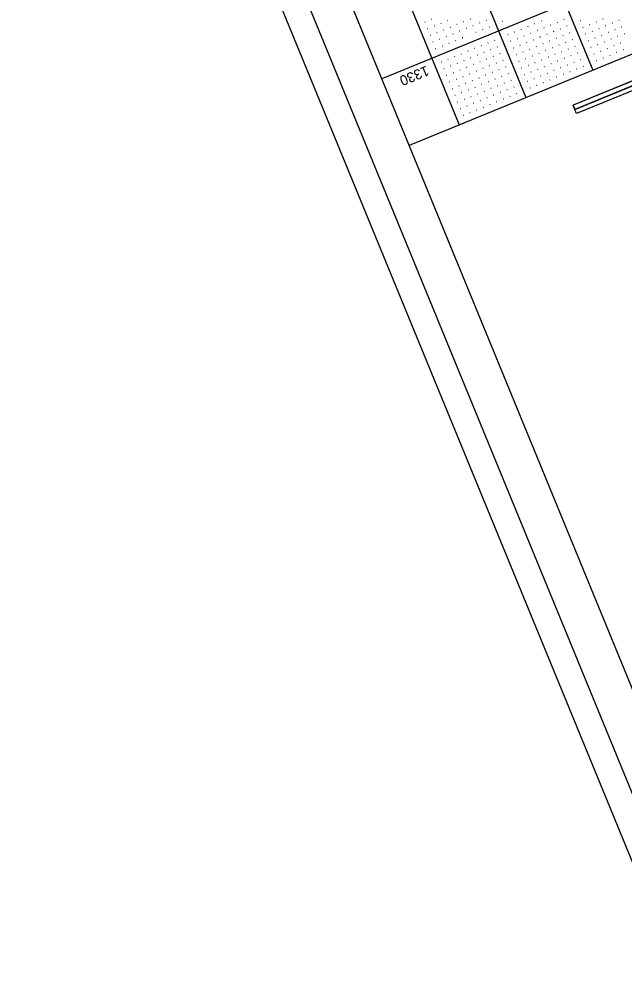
# Model space of a CAD drawing. Extents: x 2148770 to 2150891, y 142633 to 144465.
# Drawn here: x 2148770 to 2149190, y 142633 to 143292 of the extents above; entities that cross this region are included whole.
import ezdxf

# ---------------------------------------------------------------- set-up
doc = ezdxf.new("R2010")
doc.units = 0
for name, color, linetype in [('SHT_Plan_Profile_Sheet_Elev_Txt', 7, 'Continuous'), ('SHT_Plot_Shape_Full', 7, 'Continuous'), ('SHT_Plot_Shape_Half', 7, 'Continuous'), ('SHT_Profile_Grid_Major', 7, 'Continuous'), ('SHT_Profile_Grid_Minor', 7, 'Continuous'), ('SHT_Scale', 7, 'Continuous'), ('SHT_Sheet_Border', 7, 'Continuous')]:
    doc.layers.add(name, color=color, linetype=linetype)

msp = doc.modelspace()

# ---------------------------------------------------------------- linework, layer by layer
at = {"layer": 'SHT_Plot_Shape_Full'}
msp.add_lwpolyline([(2150890.55, 143316.95), (2149225.42, 142633.31), (2148769.66, 143743.39), (2150434.78, 144427.04)], close=True, dxfattribs=at)
at = {"layer": 'SHT_Plot_Shape_Half'}
msp.add_lwpolyline([(2150799.14, 143324.02), (2149226.52, 142678.36), (2148808.74, 143695.93), (2150381.36, 144341.59)], close=True, dxfattribs=at)
at = {"layer": 'SHT_Profile_Grid_Major'}
for p, q in [((2150478.22, 143848.96), (2149021.23, 143250.78)), ((2149015.5, 143626.78), (2149167.42, 143256.75)), ((2148969.25, 143607.79), (2149121.17, 143237.76))]:
    msp.add_line(p, q, dxfattribs=at)
at = {"layer": 'SHT_Profile_Grid_Minor'}
for p, q in [((2149051.17, 143290.09), (2149050.94, 143290)), ((2149055.79, 143291.99), (2149055.56, 143291.9)), ((2149066.94, 143291.17), (2149066.71, 143291.07)), ((2149078.09, 143290.34), (2149077.86, 143290.24)), ((2149082.72, 143292.24), (2149082.49, 143292.14)), ((2149089.24, 143289.51), (2149089.01, 143289.42)), ((2149093.87, 143291.41), (2149093.64, 143291.32)), ((2149105.02, 143290.58), (2149104.79, 143290.49)), ((2149131.94, 143290.83), (2149131.71, 143290.73)), ((2149143.09, 143290), (2149142.86, 143289.91)), ((2149147.72, 143291.9), (2149147.49, 143291.8)), ((2149158.87, 143291.07), (2149158.64, 143290.98)), ((2149170.02, 143290.24), (2149169.79, 143290.15)), ((2149174.64, 143292.14), (2149174.41, 143292.05)), ((2149181.17, 143289.42), (2149180.94, 143289.32)), ((2149185.79, 143291.32), (2149185.56, 143291.22)), ((2149053.07, 143285.47), (2149052.84, 143285.37)), ((2149057.69, 143287.37), (2149057.46, 143287.27)), ((2149059.59, 143282.74), (2149059.36, 143282.65)), ((2149062.32, 143289.27), (2149062.09, 143289.17)), ((2149064.22, 143284.64), (2149063.99, 143284.55)), ((2149068.84, 143286.54), (2149068.61, 143286.45)), ((2149073.47, 143288.44), (2149073.24, 143288.34)), ((2149075.37, 143283.81), (2149075.14, 143283.72)), ((2149079.99, 143285.71), (2149079.76, 143285.62)), ((2149084.62, 143287.61), (2149084.39, 143287.52)), ((2149086.52, 143282.99), (2149086.29, 143282.89)), ((2149091.14, 143284.89), (2149090.91, 143284.79)), ((2149095.77, 143286.79), (2149095.54, 143286.69)), ((2149113.44, 143283.23), (2149113.21, 143283.14)), ((2149118.07, 143285.13), (2149117.84, 143285.04)), ((2149122.69, 143287.03), (2149122.46, 143286.93)), ((2149127.32, 143288.93), (2149127.09, 143288.83)), ((2149129.22, 143284.3), (2149128.99, 143284.21)), ((2149133.84, 143286.2), (2149133.61, 143286.11)), ((2149138.47, 143288.1), (2149138.24, 143288.01)), ((2149140.37, 143283.48), (2149140.13, 143283.38)), ((2149144.99, 143285.37), (2149144.76, 143285.28)), ((2149149.62, 143287.27), (2149149.39, 143287.18)), ((2149160.77, 143286.45), (2149160.54, 143286.35)), ((2149165.39, 143288.35), (2149165.16, 143288.25)), ((2149167.29, 143283.72), (2149167.06, 143283.63)), ((2149171.92, 143285.62), (2149171.68, 143285.52)), ((2149176.54, 143287.52), (2149176.31, 143287.42)), ((2149178.44, 143282.89), (2149178.21, 143282.8)), ((2149183.07, 143284.79), (2149182.83, 143284.7)), ((2149187.69, 143286.69), (2149187.46, 143286.6)), ((2149054.97, 143280.84), (2149054.74, 143280.75)), ((2149056.87, 143276.22), (2149056.63, 143276.12)), ((2149061.49, 143278.12), (2149061.26, 143278.02)), ((2149066.12, 143280.02), (2149065.89, 143279.92)), ((2149070.74, 143281.92), (2149070.51, 143281.82)), ((2149072.64, 143277.29), (2149072.41, 143277.2)), ((2149077.27, 143279.19), (2149077.03, 143279.09)), ((2149081.89, 143281.09), (2149081.66, 143280.99)), ((2149099.57, 143277.53), (2149099.33, 143277.44)), ((2149108.82, 143281.33), (2149108.58, 143281.24)), ((2149110.72, 143276.71), (2149110.48, 143276.61)), ((2149115.34, 143278.61), (2149115.11, 143278.51)), ((2149119.97, 143280.51), (2149119.73, 143280.41)), ((2149124.59, 143282.4), (2149124.36, 143282.31)), ((2149126.49, 143277.78), (2149126.26, 143277.68)), ((2149131.12, 143279.68), (2149130.88, 143279.58)), ((2149135.74, 143281.58), (2149135.51, 143281.48)), ((2149137.64, 143276.95), (2149137.41, 143276.86)), ((2149142.27, 143278.85), (2149142.03, 143278.76)), ((2149146.89, 143280.75), (2149146.66, 143280.65)), ((2149148.79, 143276.12), (2149148.56, 143276.03)), ((2149151.52, 143282.65), (2149151.28, 143282.55)), ((2149153.41, 143278.02), (2149153.18, 143277.93)), ((2149162.67, 143281.82), (2149162.43, 143281.73)), ((2149164.56, 143277.2), (2149164.33, 143277.1)), ((2149169.19, 143279.09), (2149168.96, 143279)), ((2149173.82, 143280.99), (2149173.58, 143280.9)), ((2149175.71, 143276.37), (2149175.48, 143276.27)), ((2149180.34, 143278.27), (2149180.11, 143278.17)), ((2149184.96, 143280.17), (2149184.73, 143280.07)), ((2149189.59, 143282.07), (2149189.36, 143281.97)), ((2149058.76, 143271.59), (2149058.53, 143271.5)), ((2149063.39, 143273.49), (2149063.16, 143273.4)), ((2149068.02, 143275.39), (2149067.78, 143275.3)), ((2149081.06, 143269.94), (2149080.83, 143269.84)), ((2149085.69, 143271.84), (2149085.46, 143271.74)), ((2149090.31, 143273.74), (2149090.08, 143273.64)), ((2149094.94, 143275.64), (2149094.71, 143275.54)), ((2149096.84, 143271.01), (2149096.61, 143270.92)), ((2149101.46, 143272.91), (2149101.23, 143272.81)), ((2149112.61, 143272.08), (2149112.38, 143271.99)), ((2149117.24, 143273.98), (2149117.01, 143273.89)), ((2149121.86, 143275.88), (2149121.63, 143275.78)), ((2149123.76, 143271.25), (2149123.53, 143271.16)), ((2149128.39, 143273.15), (2149128.16, 143273.06)), ((2149133.01, 143275.05), (2149132.78, 143274.96)), ((2149134.91, 143270.43), (2149134.68, 143270.33)), ((2149139.54, 143272.33), (2149139.31, 143272.23)), ((2149144.16, 143274.23), (2149143.93, 143274.13)), ((2149146.06, 143269.6), (2149145.83, 143269.5)), ((2149150.69, 143271.5), (2149150.46, 143271.4)), ((2149155.31, 143273.4), (2149155.08, 143273.3)), ((2149166.46, 143272.57), (2149166.23, 143272.48)), ((2149171.09, 143274.47), (2149170.86, 143274.37)), ((2149172.99, 143269.84), (2149172.76, 143269.75)), ((2149177.61, 143271.74), (2149177.38, 143271.65)), ((2149182.24, 143273.64), (2149182.01, 143273.55)), ((2149186.86, 143275.54), (2149186.63, 143275.45)), ((2149188.76, 143270.92), (2149188.53, 143270.82)), ((2149067.19, 143264.24), (2149066.96, 143264.15)), ((2149071.81, 143266.14), (2149071.58, 143266.05)), ((2149076.44, 143268.04), (2149076.21, 143267.94)), ((2149078.34, 143263.41), (2149078.11, 143263.32)), ((2149082.96, 143265.31), (2149082.73, 143265.22)), ((2149087.59, 143267.21), (2149087.36, 143267.12)), ((2149092.21, 143269.11), (2149091.98, 143269.02)), ((2149094.11, 143264.49), (2149093.88, 143264.39)), ((2149098.74, 143266.38), (2149098.51, 143266.29)), ((2149103.36, 143268.28), (2149103.13, 143268.19)), ((2149105.26, 143263.66), (2149105.03, 143263.56)), ((2149114.51, 143267.46), (2149114.28, 143267.36)), ((2149119.14, 143269.36), (2149118.91, 143269.26)), ((2149121.04, 143264.73), (2149120.81, 143264.64)), ((2149125.66, 143266.63), (2149125.43, 143266.53)), ((2149130.29, 143268.53), (2149130.06, 143268.43)), ((2149132.19, 143263.9), (2149131.96, 143263.81)), ((2149136.81, 143265.8), (2149136.58, 143265.71)), ((2149141.44, 143267.7), (2149141.21, 143267.61)), ((2149143.34, 143263.08), (2149143.11, 143262.98)), ((2149147.96, 143264.97), (2149147.73, 143264.88)), ((2149152.59, 143266.87), (2149152.36, 143266.78)), ((2149157.21, 143268.77), (2149156.98, 143268.68)), ((2149159.11, 143264.15), (2149158.88, 143264.05)), ((2149168.36, 143267.95), (2149168.13, 143267.85)), ((2149170.26, 143263.32), (2149170.03, 143263.22)), ((2149174.89, 143265.22), (2149174.66, 143265.12)), ((2149179.51, 143267.12), (2149179.28, 143267.02)), ((2149184.14, 143269.02), (2149183.91, 143268.92)), ((2149062.56, 143262.34), (2149062.33, 143262.25)), ((2149064.46, 143257.72), (2149064.23, 143257.62)), ((2149069.09, 143259.62), (2149068.86, 143259.52)), ((2149073.71, 143261.52), (2149073.48, 143261.42)), ((2149075.61, 143256.89), (2149075.38, 143256.79)), ((2149080.24, 143258.79), (2149080.01, 143258.69)), ((2149084.86, 143260.69), (2149084.63, 143260.59)), ((2149089.49, 143262.59), (2149089.26, 143262.49)), ((2149091.39, 143257.96), (2149091.16, 143257.87)), ((2149096.01, 143259.86), (2149095.78, 143259.77)), ((2149100.64, 143261.76), (2149100.41, 143261.66)), ((2149102.54, 143257.13), (2149102.3, 143257.04)), ((2149107.16, 143259.03), (2149106.93, 143258.94)), ((2149116.41, 143262.83), (2149116.18, 143262.74)), ((2149118.31, 143258.21), (2149118.08, 143258.11)), ((2149122.94, 143260.1), (2149122.71, 143260.01)), ((2149127.56, 143262), (2149127.33, 143261.91)), ((2149129.46, 143257.38), (2149129.23, 143257.28)), ((2149134.09, 143259.28), (2149133.85, 143259.18)), ((2149138.71, 143261.18), (2149138.48, 143261.08)), ((2149140.61, 143256.55), (2149140.38, 143256.46)), ((2149145.24, 143258.45), (2149145, 143258.36)), ((2149149.86, 143260.35), (2149149.63, 143260.25)), ((2149154.49, 143262.25), (2149154.26, 143262.15)), ((2149156.39, 143257.62), (2149156.15, 143257.53)), ((2149161.01, 143259.52), (2149160.78, 143259.43)), ((2149066.36, 143253.09), (2149066.13, 143253)), ((2149070.99, 143254.99), (2149070.75, 143254.9)), ((2149072.89, 143250.37), (2149072.65, 143250.27)), ((2149077.51, 143252.26), (2149077.28, 143252.17)), ((2149082.14, 143254.16), (2149081.9, 143254.07)), ((2149086.76, 143256.06), (2149086.53, 143255.97)), ((2149088.66, 143251.44), (2149088.43, 143251.34)), ((2149093.29, 143253.34), (2149093.05, 143253.24)), ((2149097.91, 143255.24), (2149097.68, 143255.14)), ((2149099.81, 143250.61), (2149099.58, 143250.51)), ((2149104.44, 143252.51), (2149104.2, 143252.41)), ((2149109.06, 143254.41), (2149108.83, 143254.31)), ((2149110.96, 143249.78), (2149110.73, 143249.69)), ((2149120.21, 143253.58), (2149119.98, 143253.49)), ((2149124.84, 143255.48), (2149124.6, 143255.38)), ((2149126.73, 143250.85), (2149126.5, 143250.76)), ((2149131.36, 143252.75), (2149131.13, 143252.66)), ((2149135.99, 143254.65), (2149135.75, 143254.56)), ((2149137.88, 143250.03), (2149137.65, 143249.93)), ((2149142.51, 143251.93), (2149142.28, 143251.83)), ((2149147.13, 143253.82), (2149146.9, 143253.73)), ((2149151.76, 143255.72), (2149151.53, 143255.63)), ((2149068.26, 143248.47), (2149068.03, 143248.37)), ((2149070.16, 143243.84), (2149069.93, 143243.75)), ((2149074.78, 143245.74), (2149074.55, 143245.65)), ((2149079.41, 143247.64), (2149079.18, 143247.54)), ((2149084.03, 143249.54), (2149083.8, 143249.44)), ((2149085.93, 143244.91), (2149085.7, 143244.82)), ((2149090.56, 143246.81), (2149090.33, 143246.72)), ((2149095.18, 143248.71), (2149094.95, 143248.62)), ((2149097.08, 143244.09), (2149096.85, 143243.99)), ((2149101.71, 143245.98), (2149101.48, 143245.89)), ((2149106.33, 143247.88), (2149106.1, 143247.79)), ((2149108.23, 143243.26), (2149108, 143243.16)), ((2149112.86, 143245.16), (2149112.63, 143245.06)), ((2149122.11, 143248.96), (2149121.88, 143248.86)), ((2149124.01, 143244.33), (2149123.78, 143244.23)), ((2149128.63, 143246.23), (2149128.4, 143246.13)), ((2149133.26, 143248.13), (2149133.03, 143248.03)), ((2149072.06, 143239.22), (2149071.83, 143239.12)), ((2149076.68, 143241.11), (2149076.45, 143241.02)), ((2149081.31, 143243.01), (2149081.08, 143242.92)), ((2149083.21, 143238.39), (2149082.98, 143238.29)), ((2149087.83, 143240.29), (2149087.6, 143240.19)), ((2149092.46, 143242.19), (2149092.23, 143242.09)), ((2149094.36, 143237.56), (2149094.13, 143237.47)), ((2149098.98, 143239.46), (2149098.75, 143239.37)), ((2149103.61, 143241.36), (2149103.38, 143241.26)), ((2149105.51, 143236.73), (2149105.28, 143236.64)), ((2149110.13, 143238.63), (2149109.9, 143238.54)), ((2149114.76, 143240.53), (2149114.53, 143240.44)), ((2149073.96, 143234.59), (2149073.73, 143234.5)), ((2149078.58, 143236.49), (2149078.35, 143236.39)), ((2149080.48, 143231.86), (2149080.25, 143231.77)), ((2149085.11, 143233.76), (2149084.88, 143233.67)), ((2149089.73, 143235.66), (2149089.5, 143235.57)), ((2149091.63, 143231.04), (2149091.4, 143230.94)), ((2149096.26, 143232.94), (2149096.02, 143232.84)), ((2149100.88, 143234.83), (2149100.65, 143234.74)), ((2149075.86, 143229.97), (2149075.62, 143229.87)), ((2149077.75, 143225.34), (2149077.52, 143225.24)), ((2149082.38, 143227.24), (2149082.15, 143227.14)), ((2149087.01, 143229.14), (2149086.77, 143229.04))]:
    msp.add_line(p, q, dxfattribs=at)
at = {"layer": 'SHT_Scale'}
for p, q in [((2149292.32, 143289.28), (2149153.89, 143232.45)), ((2149294.69, 143283.5), (2149156.27, 143226.67)), ((2149247.36, 143267.44), (2149155.08, 143229.56)), ((2149200.03, 143251.39), (2149153.89, 143232.45)), ((2149155.08, 143229.56), (2149201.22, 143248.5)), ((2149155.08, 143229.56), (2149153.89, 143232.45)), ((2149153.89, 143232.45), (2149155.08, 143229.56)), ((2149156.27, 143226.67), (2149155.08, 143229.56))]:
    msp.add_line(p, q, dxfattribs=at)
at = {"layer": 'SHT_Sheet_Border'}
for p, q in [((2150497.21, 143802.71), (2149040.22, 143204.53)), ((2148894.51, 143658.18), (2149074.91, 143218.77))]:
    msp.add_line(p, q, dxfattribs=at)
msp.add_lwpolyline([(2150699.45, 143310.11), (2149242.47, 142711.93), (2148843.68, 143683.25), (2150300.66, 144281.43)], close=True, dxfattribs=at)

# ---------------------------------------------------------------- texts
at = {"layer": 'SHT_Plan_Profile_Sheet_Elev_Txt'}
msp.add_text('1330', height=7, rotation=202.32131, dxfattribs=at).set_placement((2149052.13, 143260.05))

doc.saveas('drawing.dxf')
